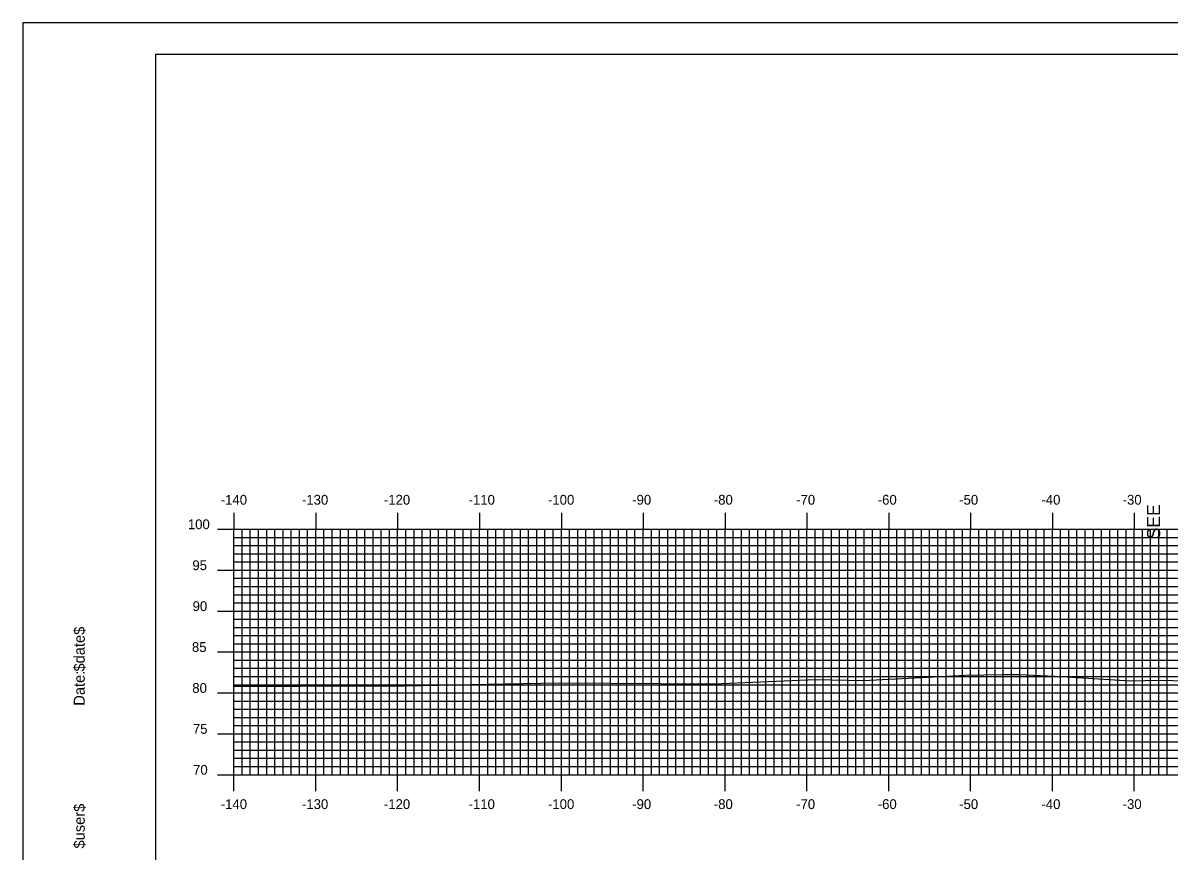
# Model space of a CAD drawing. Extents: x 853329 to 853673, y 364366 to 364586.
# Drawn here: x 853329.4 to 853469.5, y 364484.5 to 364585.7 of the extents above; entities that cross this region are included whole.
import ezdxf

# ---------------------------------------------------------------- set-up
doc = ezdxf.new("R2010")
doc.units = 0
for name, color, linetype in [('ANNOTATION', 7, 'Continuous'), ('BORDER', 7, 'Continuous'), ('H_V ANNOTATION', 7, 'Continuous'), ('MAJOR', 7, 'Continuous'), ('MINOR', 7, 'Continuous'), ('PLOT BOUNDARY', 7, 'Continuous'), ('S_Roadway_Centerline', 7, 'Continuous')]:
    doc.layers.add(name, color=color, linetype=linetype)

msp = doc.modelspace()

# ---------------------------------------------------------------- linework, layer by layer
at = {"layer": 'BORDER'}
msp.add_lwpolyline([(853345.6, 364371.79), (853665.6, 364371.79), (853665.6, 364581.79), (853345.6, 364581.79)], close=True, dxfattribs=at)
at = {"layer": 'MAJOR'}
for p, q in [((853355.2, 364525.79), (853355.2, 364523.79)), ((853365.2, 364525.79), (853365.2, 364523.79)), ((853375.2, 364525.79), (853375.2, 364523.79)), ((853385.2, 364525.79), (853385.2, 364523.79)), ((853395.2, 364525.79), (853395.2, 364523.79)), ((853405.2, 364525.79), (853405.2, 364523.79)), ((853415.2, 364525.79), (853415.2, 364523.79)), ((853425.2, 364525.79), (853425.2, 364523.79)), ((853435.2, 364525.79), (853435.2, 364523.79)), ((853445.2, 364525.79), (853445.2, 364523.79)), ((853455.2, 364525.79), (853455.2, 364523.79)), ((853465.2, 364525.79), (853465.2, 364523.79)), ((853353.2, 364523.79), (853355.2, 364523.79)), ((853355.2, 364523.79), (853635.2, 364523.79)), ((853355.2, 364493.79), (853355.2, 364523.79)), ((853355.2, 364493.79), (853355.2, 364523.79)), ((853355.2, 364523.79), (853635.2, 364523.79)), ((853365.2, 364493.79), (853365.2, 364523.79)), ((853375.2, 364493.79), (853375.2, 364523.79)), ((853385.2, 364493.79), (853385.2, 364523.79)), ((853395.2, 364493.79), (853395.2, 364523.79)), ((853405.2, 364493.79), (853405.2, 364523.79)), ((853415.2, 364493.79), (853415.2, 364523.79)), ((853425.2, 364493.79), (853425.2, 364523.79)), ((853435.2, 364493.79), (853435.2, 364523.79)), ((853445.2, 364493.79), (853445.2, 364523.79)), ((853455.2, 364493.79), (853455.2, 364523.79)), ((853465.2, 364493.79), (853465.2, 364523.79)), ((853353.2, 364518.79), (853355.2, 364518.79)), ((853355.2, 364518.79), (853635.2, 364518.79)), ((853353.2, 364513.79), (853355.2, 364513.79)), ((853355.2, 364513.79), (853635.2, 364513.79)), ((853353.2, 364508.79), (853355.2, 364508.79)), ((853355.2, 364508.79), (853635.2, 364508.79)), ((853353.2, 364503.79), (853355.2, 364503.79)), ((853355.2, 364503.79), (853635.2, 364503.79)), ((853353.2, 364498.79), (853355.2, 364498.79)), ((853355.2, 364498.79), (853635.2, 364498.79)), ((853353.2, 364493.79), (853355.2, 364493.79)), ((853355.2, 364493.79), (853635.2, 364493.79)), ((853355.2, 364493.79), (853635.2, 364493.79)), ((853355.2, 364491.78), (853355.2, 364493.79)), ((853365.2, 364491.78), (853365.2, 364493.79)), ((853375.2, 364491.78), (853375.2, 364493.79)), ((853385.2, 364491.78), (853385.2, 364493.79)), ((853395.2, 364491.78), (853395.2, 364493.79)), ((853405.2, 364491.78), (853405.2, 364493.79)), ((853415.2, 364491.78), (853415.2, 364493.79)), ((853425.2, 364491.78), (853425.2, 364493.79)), ((853435.2, 364491.78), (853435.2, 364493.79)), ((853445.2, 364491.78), (853445.2, 364493.79)), ((853455.2, 364491.78), (853455.2, 364493.79)), ((853465.2, 364491.78), (853465.2, 364493.79))]:
    msp.add_line(p, q, dxfattribs=at)
at = {"layer": 'MINOR'}
for p, q in [((853356.2, 364493.79), (853356.2, 364523.79)), ((853357.2, 364493.79), (853357.2, 364523.79)), ((853358.2, 364493.79), (853358.2, 364523.79)), ((853359.2, 364493.79), (853359.2, 364523.79)), ((853360.2, 364493.79), (853360.2, 364523.79)), ((853361.2, 364493.79), (853361.2, 364523.79)), ((853362.2, 364493.79), (853362.2, 364523.79)), ((853363.2, 364493.79), (853363.2, 364523.79)), ((853364.2, 364493.79), (853364.2, 364523.79)), ((853366.2, 364493.79), (853366.2, 364523.79)), ((853367.2, 364493.79), (853367.2, 364523.79)), ((853368.2, 364493.79), (853368.2, 364523.79)), ((853369.2, 364493.79), (853369.2, 364523.79)), ((853370.2, 364493.79), (853370.2, 364523.79)), ((853371.2, 364493.79), (853371.2, 364523.79)), ((853372.2, 364493.79), (853372.2, 364523.79)), ((853373.2, 364493.79), (853373.2, 364523.79)), ((853374.2, 364493.79), (853374.2, 364523.79)), ((853376.2, 364493.79), (853376.2, 364523.79)), ((853377.2, 364493.79), (853377.2, 364523.79)), ((853378.2, 364493.79), (853378.2, 364523.79)), ((853379.2, 364493.79), (853379.2, 364523.79)), ((853380.2, 364493.79), (853380.2, 364523.79)), ((853381.2, 364493.79), (853381.2, 364523.79)), ((853382.2, 364493.79), (853382.2, 364523.79)), ((853383.2, 364493.79), (853383.2, 364523.79)), ((853384.2, 364493.79), (853384.2, 364523.79)), ((853386.2, 364493.79), (853386.2, 364523.79)), ((853387.2, 364493.79), (853387.2, 364523.79)), ((853388.2, 364493.79), (853388.2, 364523.79)), ((853389.2, 364493.79), (853389.2, 364523.79)), ((853390.2, 364493.79), (853390.2, 364523.79)), ((853391.2, 364493.79), (853391.2, 364523.79)), ((853392.2, 364493.79), (853392.2, 364523.79)), ((853393.2, 364493.79), (853393.2, 364523.79)), ((853394.2, 364493.79), (853394.2, 364523.79)), ((853396.2, 364493.79), (853396.2, 364523.79)), ((853397.2, 364493.79), (853397.2, 364523.79)), ((853398.2, 364493.79), (853398.2, 364523.79)), ((853399.2, 364493.79), (853399.2, 364523.79)), ((853400.2, 364493.79), (853400.2, 364523.79)), ((853401.2, 364493.79), (853401.2, 364523.79)), ((853402.2, 364493.79), (853402.2, 364523.79)), ((853403.2, 364493.79), (853403.2, 364523.79)), ((853404.2, 364493.79), (853404.2, 364523.79)), ((853406.2, 364493.79), (853406.2, 364523.79)), ((853407.2, 364493.79), (853407.2, 364523.79)), ((853408.2, 364493.79), (853408.2, 364523.79)), ((853409.2, 364493.79), (853409.2, 364523.79)), ((853410.2, 364493.79), (853410.2, 364523.79)), ((853411.2, 364493.79), (853411.2, 364523.79)), ((853412.2, 364493.79), (853412.2, 364523.79)), ((853413.2, 364493.79), (853413.2, 364523.79)), ((853414.2, 364493.79), (853414.2, 364523.79)), ((853416.2, 364493.79), (853416.2, 364523.79)), ((853417.2, 364493.79), (853417.2, 364523.79)), ((853418.2, 364493.79), (853418.2, 364523.79)), ((853419.2, 364493.79), (853419.2, 364523.79)), ((853420.2, 364493.79), (853420.2, 364523.79)), ((853421.2, 364493.79), (853421.2, 364523.79)), ((853422.2, 364493.79), (853422.2, 364523.79)), ((853423.2, 364493.79), (853423.2, 364523.79)), ((853424.2, 364493.79), (853424.2, 364523.79)), ((853426.2, 364493.79), (853426.2, 364523.79)), ((853427.2, 364493.79), (853427.2, 364523.79)), ((853428.2, 364493.79), (853428.2, 364523.79)), ((853429.2, 364493.79), (853429.2, 364523.79)), ((853430.2, 364493.79), (853430.2, 364523.79)), ((853431.2, 364493.79), (853431.2, 364523.79)), ((853432.2, 364493.79), (853432.2, 364523.79)), ((853433.2, 364493.79), (853433.2, 364523.79)), ((853434.2, 364493.79), (853434.2, 364523.79)), ((853436.2, 364493.79), (853436.2, 364523.79)), ((853437.2, 364493.79), (853437.2, 364523.79)), ((853438.2, 364493.79), (853438.2, 364523.79)), ((853439.2, 364493.79), (853439.2, 364523.79)), ((853440.2, 364493.79), (853440.2, 364523.79)), ((853441.2, 364493.79), (853441.2, 364523.79)), ((853442.2, 364493.79), (853442.2, 364523.79)), ((853443.2, 364493.79), (853443.2, 364523.79)), ((853444.2, 364493.79), (853444.2, 364523.79)), ((853446.2, 364493.79), (853446.2, 364523.79)), ((853447.2, 364493.79), (853447.2, 364523.79)), ((853448.2, 364493.79), (853448.2, 364523.79)), ((853449.2, 364493.79), (853449.2, 364523.79)), ((853450.2, 364493.79), (853450.2, 364523.79)), ((853451.2, 364493.79), (853451.2, 364523.79)), ((853452.2, 364493.79), (853452.2, 364523.79)), ((853453.2, 364493.79), (853453.2, 364523.79)), ((853454.2, 364493.79), (853454.2, 364523.79)), ((853456.2, 364493.79), (853456.2, 364523.79)), ((853457.2, 364493.79), (853457.2, 364523.79)), ((853458.2, 364493.79), (853458.2, 364523.79)), ((853459.2, 364493.79), (853459.2, 364523.79)), ((853460.2, 364493.79), (853460.2, 364523.79)), ((853461.2, 364493.79), (853461.2, 364523.79)), ((853462.2, 364493.79), (853462.2, 364523.79)), ((853463.2, 364493.79), (853463.2, 364523.79)), ((853464.2, 364493.79), (853464.2, 364523.79)), ((853466.2, 364493.79), (853466.2, 364523.79)), ((853467.2, 364493.79), (853467.2, 364523.79)), ((853468.2, 364493.79), (853468.2, 364523.79)), ((853469.2, 364493.79), (853469.2, 364523.79)), ((853355.2, 364522.79), (853635.2, 364522.79)), ((853355.2, 364522.79), (853357.21, 364522.79)), ((853355.2, 364521.79), (853635.2, 364521.79)), ((853355.2, 364521.79), (853357.21, 364521.79)), ((853355.2, 364520.79), (853635.2, 364520.79)), ((853355.2, 364520.79), (853357.21, 364520.79)), ((853355.2, 364519.79), (853635.2, 364519.79)), ((853355.2, 364519.79), (853357.21, 364519.79)), ((853355.2, 364517.79), (853635.2, 364517.79)), ((853355.2, 364517.79), (853357.21, 364517.79)), ((853355.2, 364516.79), (853635.2, 364516.79)), ((853355.2, 364516.79), (853357.21, 364516.79)), ((853355.2, 364515.79), (853635.2, 364515.79)), ((853355.2, 364515.79), (853357.21, 364515.79)), ((853355.2, 364514.79), (853635.2, 364514.79)), ((853355.2, 364514.79), (853357.21, 364514.79)), ((853355.2, 364512.79), (853635.2, 364512.79)), ((853355.2, 364512.79), (853357.21, 364512.79)), ((853355.2, 364511.79), (853635.2, 364511.79)), ((853355.2, 364511.79), (853357.21, 364511.79)), ((853355.2, 364510.79), (853635.2, 364510.79)), ((853355.2, 364510.79), (853357.21, 364510.79)), ((853355.2, 364509.79), (853635.2, 364509.79)), ((853355.2, 364509.79), (853357.21, 364509.79)), ((853355.2, 364507.79), (853635.2, 364507.79)), ((853355.2, 364507.79), (853357.21, 364507.79)), ((853355.2, 364506.79), (853635.2, 364506.79)), ((853355.2, 364506.79), (853357.21, 364506.79)), ((853355.2, 364505.79), (853635.2, 364505.79)), ((853355.2, 364505.79), (853357.21, 364505.79)), ((853355.2, 364504.79), (853635.2, 364504.79)), ((853355.2, 364504.79), (853357.21, 364504.79)), ((853355.2, 364502.79), (853635.2, 364502.79)), ((853355.2, 364502.79), (853357.21, 364502.79)), ((853355.2, 364501.79), (853635.2, 364501.79)), ((853355.2, 364501.79), (853357.21, 364501.79)), ((853355.2, 364500.79), (853635.2, 364500.79)), ((853355.2, 364500.79), (853357.21, 364500.79)), ((853355.2, 364499.79), (853635.2, 364499.79)), ((853355.2, 364499.79), (853357.21, 364499.79)), ((853355.2, 364497.79), (853635.2, 364497.79)), ((853355.2, 364497.79), (853357.21, 364497.79)), ((853355.2, 364496.79), (853635.2, 364496.79)), ((853355.2, 364496.79), (853357.21, 364496.79)), ((853355.2, 364495.79), (853635.2, 364495.79)), ((853355.2, 364495.79), (853357.21, 364495.79)), ((853355.2, 364494.79), (853635.2, 364494.79)), ((853355.2, 364494.79), (853357.21, 364494.79))]:
    msp.add_line(p, q, dxfattribs=at)
at = {"layer": 'PLOT BOUNDARY'}
msp.add_lwpolyline([(853329.42, 364365.67), (853669.42, 364365.67), (853669.42, 364585.67), (853329.42, 364585.67)], close=True, dxfattribs=at)
at = {"layer": 'S_Roadway_Centerline'}
msp.add_lwpolyline([(853355.2, 364504.62), (853359.94, 364504.61), (853363.36, 364504.61), (853370.85, 364504.64), (853376, 364504.66), (853378.09, 364504.68), (853388.36, 364504.91), (853394.89, 364505), (853413.68, 364504.9), (853413.79, 364504.91), (853413.83, 364504.9), (853426.25, 364505.42), (853432.11, 364505.29), (853444.58, 364505.96), (853449.04, 364506.04), (853451.13, 364506.04), (853456.36, 364505.8), (853464.71, 364505.26), (853468.35, 364505.35), (853476.14, 364505.13)], dxfattribs=at)

# ---------------------------------------------------------------- texts
at = {"layer": 'ANNOTATION'}
msp.add_text('SEE', height=1.6, rotation=90, dxfattribs=at).set_placement((853468.36, 364522.56))
at = {"layer": 'BORDER'}
for s, p in [('$date$', (853336.97, 364506.4)), ('Date:', (853336.97, 364502.22)), ('$user$', (853336.97, 364484.77))]:
    msp.add_text(s, height=1.339, rotation=90, dxfattribs=at).set_placement(p)
at = {"layer": 'H_V ANNOTATION'}
for s, p in [('-140', (853353.59, 364526.79)), ('-130', (853363.51, 364526.79)), ('-120', (853373.52, 364526.79)), ('-110', (853383.87, 364526.79)), ('-100', (853393.57, 364526.79)), ('-90', (853403.86, 364526.79)), ('-80', (853413.83, 364526.79)), ('-70', (853423.89, 364526.79)), ('-60', (853433.86, 364526.79)), ('-50', (853443.81, 364526.79)), ('-40', (853453.86, 364526.79)), ('-30', (853463.78, 364526.79)), ('100', (853349.57, 364523.79)), ('95', (853350.12, 364518.79)), ('90', (853350.15, 364513.79)), ('85', (853350.07, 364508.79)), ('80', (853350.11, 364503.79)), ('75', (853350.18, 364498.79)), ('70', (853350.21, 364493.79)), ('-140', (853353.59, 364489.59)), ('-130', (853363.51, 364489.59)), ('-120', (853373.52, 364489.59)), ('-110', (853383.87, 364489.59)), ('-100', (853393.57, 364489.59)), ('-90', (853403.86, 364489.59)), ('-80', (853413.83, 364489.59)), ('-70', (853423.89, 364489.59)), ('-60', (853433.86, 364489.59)), ('-50', (853443.81, 364489.59)), ('-40', (853453.86, 364489.59)), ('-30', (853463.78, 364489.59))]:
    msp.add_text(s, height=1.2, dxfattribs=at).set_placement(p)
at = {"layer": 'MAJOR'}
msp.add_text('-', height=0.012, dxfattribs=at).set_placement((853355.2, 364493.79))

doc.saveas('drawing.dxf')
